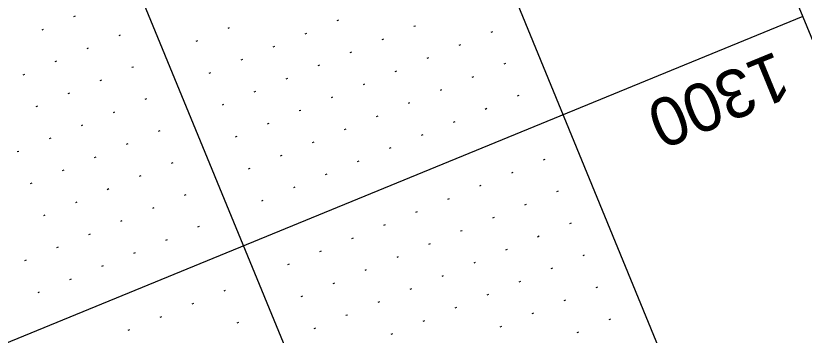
# Model space of a CAD drawing. Extents: x 2148770 to 2150891, y 142633 to 144465.
# Drawn here: x 2150307.4 to 2150421.5, y 143941.5 to 143987.8 of the extents above; entities that cross this region are included whole.
import ezdxf

# ---------------------------------------------------------------- set-up
doc = ezdxf.new("R2010")
doc.units = 0
for name, color, linetype in [('SHT_Plan_Profile_Sheet_Elev_Txt', 7, 'Continuous'), ('SHT_Profile_Grid_Major', 7, 'Continuous'), ('SHT_Profile_Grid_Minor', 7, 'Continuous'), ('SHT_Sheet_Border', 7, 'Continuous')]:
    doc.layers.add(name, color=color, linetype=linetype)

msp = doc.modelspace()

# ---------------------------------------------------------------- linework, layer by layer
at = {"layer": 'SHT_Profile_Grid_Major'}
for p, q in [((2150226.36, 144232.01), (2150416.26, 143769.48)), ((2150421.25, 143987.72), (2148964.26, 143389.54))]:
    msp.add_line(p, q, dxfattribs=at)
at = {"layer": 'SHT_Profile_Grid_Minor'}
for p, q in [((2150315.97, 143987.74), (2150315.74, 143987.65)), ((2150354.05, 143987.16), (2150353.82, 143987.07)), ((2150365.2, 143986.33), (2150364.97, 143986.24)), ((2150311.35, 143985.85), (2150311.12, 143985.75)), ((2150338.27, 143986.09), (2150338.04, 143985.99)), ((2150349.42, 143985.26), (2150349.19, 143985.17)), ((2150376.35, 143985.51), (2150376.12, 143985.41)), ((2150322.5, 143985.02), (2150322.27, 143984.92)), ((2150333.65, 143984.19), (2150333.42, 143984.1)), ((2150360.57, 143984.44), (2150360.34, 143984.34)), ((2150317.87, 143983.12), (2150317.64, 143983.02)), ((2150344.8, 143983.36), (2150344.57, 143983.27)), ((2150371.72, 143983.61), (2150371.49, 143983.51)), ((2150355.95, 143982.54), (2150355.72, 143982.44)), ((2150313.25, 143981.22), (2150313.02, 143981.13)), ((2150340.17, 143981.46), (2150339.94, 143981.37)), ((2150351.32, 143980.64), (2150351.09, 143980.54)), ((2150367.1, 143981.71), (2150366.87, 143981.61)), ((2150378.25, 143980.88), (2150378.02, 143980.79)), ((2150324.4, 143980.39), (2150324.17, 143980.3)), ((2150335.55, 143979.57), (2150335.32, 143979.47)), ((2150362.47, 143979.81), (2150362.24, 143979.71)), ((2150308.62, 143979.32), (2150308.39, 143979.23)), ((2150319.77, 143978.49), (2150319.54, 143978.4)), ((2150346.7, 143978.74), (2150346.47, 143978.64)), ((2150373.62, 143978.98), (2150373.39, 143978.89)), ((2150357.85, 143977.91), (2150357.62, 143977.82)), ((2150315.15, 143976.59), (2150314.92, 143976.5)), ((2150342.07, 143976.84), (2150341.84, 143976.74)), ((2150369, 143977.08), (2150368.77, 143976.99)), ((2150380.15, 143976.26), (2150379.92, 143976.16)), ((2150326.3, 143975.77), (2150326.07, 143975.67)), ((2150337.45, 143974.94), (2150337.22, 143974.85)), ((2150353.22, 143976.01), (2150352.99, 143975.92)), ((2150364.37, 143975.18), (2150364.14, 143975.09)), ((2150310.52, 143974.7), (2150310.29, 143974.6)), ((2150321.67, 143973.87), (2150321.44, 143973.77)), ((2150348.6, 143974.11), (2150348.37, 143974.02)), ((2150375.52, 143974.36), (2150375.29, 143974.26)), ((2150359.75, 143973.29), (2150359.51, 143973.19)), ((2150317.05, 143971.97), (2150316.82, 143971.87)), ((2150343.97, 143972.21), (2150343.74, 143972.12)), ((2150370.9, 143972.46), (2150370.66, 143972.36)), ((2150328.2, 143971.14), (2150327.96, 143971.05)), ((2150355.12, 143971.39), (2150354.89, 143971.29)), ((2150366.27, 143970.56), (2150366.04, 143970.46)), ((2150312.42, 143970.07), (2150312.19, 143969.98)), ((2150323.57, 143969.24), (2150323.34, 143969.15)), ((2150339.35, 143970.31), (2150339.11, 143970.22)), ((2150350.5, 143969.49), (2150350.26, 143969.39)), ((2150307.8, 143968.17), (2150307.56, 143968.08)), ((2150361.65, 143968.66), (2150361.41, 143968.57)), ((2150318.95, 143967.34), (2150318.71, 143967.25)), ((2150345.87, 143967.59), (2150345.64, 143967.49)), ((2150383.94, 143967.01), (2150383.71, 143966.91)), ((2150330.1, 143966.52), (2150329.86, 143966.42)), ((2150357.02, 143966.76), (2150356.79, 143966.67)), ((2150314.32, 143965.45), (2150314.09, 143965.35)), ((2150341.24, 143965.69), (2150341.01, 143965.59)), ((2150352.39, 143964.86), (2150352.16, 143964.77)), ((2150379.32, 143965.11), (2150379.09, 143965.01)), ((2150309.69, 143963.55), (2150309.46, 143963.45)), ((2150325.47, 143964.62), (2150325.24, 143964.52)), ((2150320.84, 143962.72), (2150320.61, 143962.62)), ((2150347.77, 143962.96), (2150347.54, 143962.87)), ((2150374.69, 143963.21), (2150374.46, 143963.11)), ((2150385.84, 143962.38), (2150385.61, 143962.29)), ((2150331.99, 143961.89), (2150331.76, 143961.8)), ((2150370.07, 143961.31), (2150369.84, 143961.21)), ((2150316.22, 143960.82), (2150315.99, 143960.72)), ((2150343.14, 143961.06), (2150342.91, 143960.97)), ((2150381.22, 143960.48), (2150380.99, 143960.39)), ((2150327.37, 143959.99), (2150327.14, 143959.9)), ((2150365.44, 143959.41), (2150365.21, 143959.31)), ((2150311.59, 143958.92), (2150311.36, 143958.83)), ((2150322.74, 143958.09), (2150322.51, 143958)), ((2150376.59, 143958.58), (2150376.36, 143958.49)), ((2150333.89, 143957.27), (2150333.66, 143957.17)), ((2150360.82, 143957.51), (2150360.59, 143957.42)), ((2150371.97, 143956.68), (2150371.74, 143956.59)), ((2150387.74, 143957.75), (2150387.51, 143957.66)), ((2150318.12, 143956.19), (2150317.89, 143956.1)), ((2150356.19, 143955.61), (2150355.96, 143955.52)), ((2150383.12, 143955.86), (2150382.89, 143955.76)), ((2150329.27, 143955.37), (2150329.04, 143955.27)), ((2150367.34, 143954.78), (2150367.11, 143954.69)), ((2150313.49, 143954.3), (2150313.26, 143954.2)), ((2150324.64, 143953.47), (2150324.41, 143953.37)), ((2150351.57, 143953.71), (2150351.34, 143953.62)), ((2150378.49, 143953.96), (2150378.26, 143953.86)), ((2150308.87, 143952.4), (2150308.64, 143952.3)), ((2150362.72, 143952.88), (2150362.49, 143952.79)), ((2150389.64, 143953.13), (2150389.41, 143953.03)), ((2150320.02, 143951.57), (2150319.79, 143951.47)), ((2150346.94, 143951.81), (2150346.71, 143951.72)), ((2150358.09, 143950.99), (2150357.86, 143950.89)), ((2150373.87, 143952.06), (2150373.64, 143951.96)), ((2150385.02, 143951.23), (2150384.78, 143951.14)), ((2150369.24, 143950.16), (2150369.01, 143950.06)), ((2150315.39, 143949.67), (2150315.16, 143949.58)), ((2150353.47, 143949.09), (2150353.23, 143948.99)), ((2150380.39, 143949.33), (2150380.16, 143949.24)), ((2150310.77, 143947.77), (2150310.54, 143947.68)), ((2150337.69, 143948.02), (2150337.46, 143947.92)), ((2150364.62, 143948.26), (2150364.38, 143948.16)), ((2150391.54, 143948.5), (2150391.31, 143948.41)), ((2150348.84, 143947.19), (2150348.61, 143947.09)), ((2150375.77, 143947.43), (2150375.53, 143947.34)), ((2150386.92, 143946.6), (2150386.68, 143946.51)), ((2150333.07, 143946.12), (2150332.83, 143946.02)), ((2150359.99, 143946.36), (2150359.76, 143946.27)), ((2150371.14, 143945.53), (2150370.91, 143945.44)), ((2150328.44, 143944.22), (2150328.21, 143944.12)), ((2150355.37, 143944.46), (2150355.13, 143944.37)), ((2150382.29, 143944.71), (2150382.06, 143944.61)), ((2150339.59, 143943.39), (2150339.36, 143943.29)), ((2150366.51, 143943.63), (2150366.28, 143943.54)), ((2150393.44, 143943.88), (2150393.21, 143943.78)), ((2150323.82, 143942.32), (2150323.58, 143942.22)), ((2150350.74, 143942.56), (2150350.51, 143942.47)), ((2150377.66, 143942.81), (2150377.43, 143942.71)), ((2150388.81, 143941.98), (2150388.58, 143941.88)), ((2150361.89, 143941.74), (2150361.66, 143941.64))]:
    msp.add_line(p, q, dxfattribs=at)
at = {"layer": 'SHT_Sheet_Border'}
msp.add_line((2150272.62, 144251), (2150462.52, 143788.47), dxfattribs=at)
msp.add_lwpolyline([(2150699.45, 143310.11), (2149242.47, 142711.93), (2148843.68, 143683.25), (2150300.66, 144281.43)], close=True, dxfattribs=at)

# ---------------------------------------------------------------- texts
at = {"layer": 'SHT_Plan_Profile_Sheet_Elev_Txt'}
msp.add_text('1300', height=7, rotation=202.3213, dxfattribs=at).set_placement((2150417.45, 143982.76))

doc.saveas('drawing.dxf')
